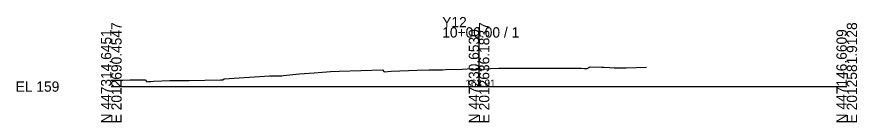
# Model space of a CAD drawing. Extents: x -26 to 1203, y -10 to 9542.
# Drawn here: x -25.7 to 202.8, y -9.7 to 19 of the extents above; entities that cross this region are included whole.
import ezdxf

# ---------------------------------------------------------------- set-up
doc = ezdxf.new("R2010")
doc.units = 0
for name, color, linetype in [('Default', 7, 'Continuous'), ('Exist Cross Section Cell', 7, 'Continuous'), ('Exist XS Center Line Elevation Label', 7, 'Continuous'), ('Exist XS Ground Line', 7, 'Continuous')]:
    doc.layers.add(name, color=color, linetype=linetype)

msp = doc.modelspace()

# ---------------------------------------------------------------- linework, layer by layer
at = {"layer": 'Exist Cross Section Cell'}
for p, q in [((100, 0), (100, 16.14)), ((0, 0), (100, 0)), ((100, 0), (200, 0))]:
    msp.add_line(p, q, dxfattribs=at)
at = {"layer": 'Exist XS Ground Line'}
msp.add_lwpolyline([(0, 1.78), (1.54, 1.78), (3.15, 1.78), (5.15, 1.79), (7.75, 1.8), (9.17, 1.8), (9.7, 1.31), (10.1, 1.35), (10.75, 1.41), (11.49, 1.44), (15.94, 1.66), (21.21, 1.68), (29.68, 1.86), (30.34, 1.8), (30.67, 2.12), (43.01, 2.88), (46.4, 2.95), (46.71, 2.97), (51.2, 3.51), (55.14, 3.75), (59.61, 4.12), (61.98, 4.22), (73.76, 4.52), (74.24, 4.03), (76.08, 4.16), (83.19, 4.44), (86.45, 4.53), (90.03, 4.57), (90.85, 4.61), (95.47, 4.75), (98.08, 4.88), (98.9, 4.67), (99.5, 4.97), (100, 4.91), (100.39, 4.87), (100.99, 4.57), (101.49, 4.74), (103.11, 4.91), (105.36, 5), (106.82, 5.01), (107.34, 5.01), (110.7, 5.01), (113.52, 4.99), (115.69, 4.97), (116.12, 4.97), (117.12, 4.97), (117.55, 4.97), (118.77, 4.98), (119.63, 4.97), (121.62, 4.98), (124.57, 4.99), (125.11, 4.99), (125.92, 5), (127.8, 4.98), (128.69, 4.96), (129.44, 4.93), (130.22, 5.38), (133.32, 5.27), (133.94, 5.24), (135.6, 5.16), (136.74, 5.12), (138.56, 5.14), (140.04, 5.12), (145.56, 5.27)], dxfattribs=at)

# ---------------------------------------------------------------- texts
at = {"layer": 'Default'}
msp.add_text('-', height=0.0001, dxfattribs=at).set_placement((0, 0))
at = {"layer": 'Exist Cross Section Cell'}
for s, p in [('Y12', (90, 16.14)), ('10+00.00 / 1', (90, 13.34)), ('EL 159', (-26, -1.4))]:
    msp.add_text(s, height=2.8, dxfattribs=at).set_placement(p)
for s, p in [('E 2012690.4547', (2.8, -10)), ('E 2012636.1837', (102.8, -10)), ('E 2012581.9128', (202.8, -10)), ('N 447314.6451', (0, -10)), ('N 447230.6530', (100, -10)), ('N 447146.6609', (200, -10))]:
    msp.add_text(s, height=2.8, rotation=90, dxfattribs=at).set_placement(p)
at = {"layer": 'Exist XS Center Line Elevation Label'}
msp.add_text('163.91', height=2, dxfattribs=at).set_placement((96.32, -0.09))

doc.saveas('drawing.dxf')
